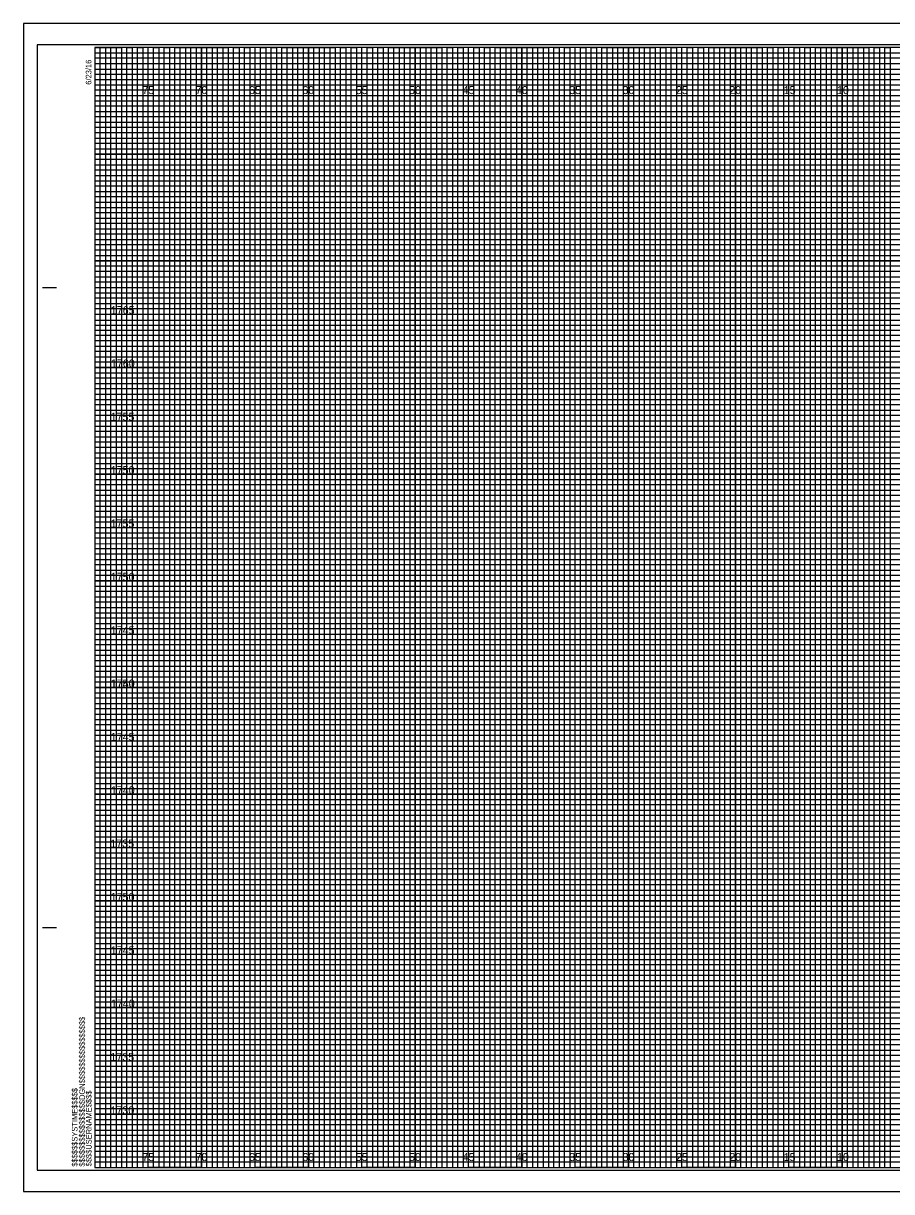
# Model space of a CAD drawing. Extents: x -7 to 162, y -2 to 217.
# Drawn here: x -6.7 to 74.6, y 107.7 to 217.2 of the extents above; entities that cross this region are included whole.
import ezdxf

# ---------------------------------------------------------------- set-up
doc = ezdxf.new("R2010")
doc.units = 0
for name, color, linetype in [('Prop XS Elevation Labels', 7, 'Continuous'), ('Prop XS Offset Labels', 7, 'Continuous'), ('Sheet Cross Section CELL', 7, 'Continuous'), ('Sheet Cross Section Grid Major CELL', 7, 'Continuous'), ('Sheet Cross Section Grid Middle CELL', 7, 'Continuous'), ('Sheet Cross Section Grid Minor 1 CELL', 7, 'Continuous'), ('Sheet Cross Section Grid Minor 2 CELL', 7, 'Continuous'), ('Sheet Cutting Line CELL', 7, 'Continuous'), ('Sheet DOT Grid CELL', 7, 'Continuous'), ('Sheet Plot Border Inside CELL', 7, 'Continuous'), ('Sheet Plot Border Outside CELL', 7, 'Continuous')]:
    doc.layers.add(name, color=color, linetype=linetype)

msp = doc.modelspace()

# ---------------------------------------------------------------- linework, layer by layer
at = {"layer": 'Sheet Cross Section CELL'}
for p, q in [((-4.9, 192.5), (-3.65, 192.5)), ((-4.85, 192.5), (-3.6, 192.5)), ((-4.9, 132.5), (-3.65, 132.5)), ((-4.85, 132.5), (-3.6, 132.5)), ((0, 110), (0, 110)), ((0, 110), (0, 110)), ((0, 110), (0, 110)), ((0, 110), (0, 110)), ((0, 110), (0, 110)), ((0, 110), (0, 110)), ((0, 110), (0, 110))]:
    msp.add_line(p, q, dxfattribs=at)
msp.add_lwpolyline([(160, 215), (0, 215), (0, 110), (160, 110)], close=True, dxfattribs=at)
at = {"layer": 'Sheet Cross Section Grid Major CELL'}
for p, q in [((5, 215), (0, 215)), ((5, 110), (5, 215)), ((15, 215), (10, 215)), ((10, 215), (10, 110)), ((15, 110), (15, 215)), ((25, 215), (20, 215)), ((20, 215), (20, 110)), ((25, 110), (25, 215)), ((35, 215), (30, 215)), ((30, 215), (30, 110)), ((35, 110), (35, 215)), ((45, 215), (40, 215)), ((40, 215), (40, 110)), ((45, 110), (45, 215)), ((55, 215), (50, 215)), ((50, 215), (50, 110)), ((55, 110), (55, 215)), ((65, 215), (60, 215)), ((60, 215), (60, 110)), ((65, 110), (65, 215)), ((75, 215), (70, 215)), ((70, 215), (70, 110)), ((10, 110), (5, 110)), ((20, 110), (15, 110)), ((30, 110), (25, 110)), ((40, 110), (35, 110)), ((50, 110), (45, 110)), ((60, 110), (55, 110)), ((70, 110), (65, 110))]:
    msp.add_line(p, q, dxfattribs=at)
for points in [[(0, 210), (160, 210), (160, 205), (0, 205)], [(0, 200), (160, 200), (160, 195), (0, 195)], [(0, 190), (160, 190), (160, 185), (0, 185)], [(0, 180), (160, 180), (160, 175), (0, 175)], [(0, 170), (160, 170), (160, 165), (0, 165)], [(0, 160), (160, 160), (160, 155), (0, 155)], [(0, 150), (160, 150), (160, 145), (0, 145)], [(0, 140), (160, 140), (160, 135), (0, 135)], [(0, 130), (160, 130), (160, 125), (0, 125)], [(0, 120), (160, 120), (160, 115), (0, 115)]]:
    msp.add_lwpolyline(points, dxfattribs=at)
at = {"layer": 'Sheet Cross Section Grid Middle CELL'}
for points in [[(0, 215), (2.5, 215), (2.5, 110), (7.5, 110), (7.5, 215), (12.5, 215), (12.5, 110), (17.5, 110), (17.5, 215), (22.5, 215), (22.5, 110), (27.5, 110), (27.5, 215), (32.5, 215), (32.5, 110), (37.5, 110), (37.5, 215), (42.5, 215), (42.5, 110), (47.5, 110), (47.5, 215), (52.5, 215), (52.5, 110), (57.5, 110), (57.5, 215), (62.5, 215), (62.5, 110), (67.5, 110), (67.5, 215), (72.5, 215), (72.5, 110), (77.5, 110)], [(0, 212.5), (137.5, 212.5)], [(0, 202.5), (160, 202.5), (160, 207.5), (0, 207.5)], [(0, 192.5), (160, 192.5), (160, 197.5), (0, 197.5)], [(0, 182.5), (160, 182.5), (160, 187.5), (0, 187.5)], [(0, 172.5), (160, 172.5), (160, 177.5), (0, 177.5)], [(0, 162.5), (160, 162.5), (160, 167.5), (0, 167.5)], [(0, 152.5), (160, 152.5), (160, 157.5), (0, 157.5)], [(0, 142.5), (160, 142.5), (160, 147.5), (0, 147.5)], [(0, 132.5), (160, 132.5), (160, 137.5), (0, 137.5)], [(0, 122.5), (160, 122.5), (160, 127.5), (0, 127.5)], [(0, 112.5), (160, 112.5), (160, 117.5), (0, 117.5)]]:
    msp.add_lwpolyline(points, dxfattribs=at)
at = {"layer": 'Sheet Cross Section Grid Minor 1 CELL'}
for p, q in [((0, 214.5), (130, 214.5)), ((130, 213.99), (0, 213.99)), ((0, 213.99), (0, 213.5)), ((0, 213.5), (130, 213.5)), ((130, 212.94), (0, 212.94)), ((0, 212.94), (0, 212)), ((0, 212), (160, 212))]:
    msp.add_line(p, q, dxfattribs=at)
for points in [[(0, 211.5), (135, 211.5), (160, 211.5), (160, 211), (0, 211)], [(0, 210.5), (160, 210.5), (160, 209.5), (0, 209.5)], [(0, 209), (160, 209), (160, 208.5), (0, 208.49)], [(0, 208), (160, 208), (160, 207), (0, 207)], [(0, 206.5), (160, 206.5), (160, 206), (0, 206)], [(0, 205.5), (160, 205.5), (160, 204.5), (0, 204.5)], [(0, 204), (160, 204), (160, 203.5), (0, 203.5)], [(0, 203), (160, 203), (160, 202), (0, 202)], [(0, 201.5), (160, 201.5), (160, 201), (0, 201)], [(0, 200.5), (160, 200.5), (160, 199.5), (0, 199.5)], [(0, 199), (160, 199), (160, 198.5), (0, 198.5)], [(0, 198), (160, 198), (160, 196.97), (160, 196.5), (160, 196), (0, 196)], [(0, 197), (160, 197), (160, 196.5), (0, 196.5)], [(0, 195.5), (160, 195.5), (160, 194.5), (0, 194.52)], [(0, 194.52), (160, 194.5), (160, 194), (0, 194)], [(0, 193.5), (160, 193.5), (160, 193), (0, 193)], [(0, 192), (160, 192), (160, 191.5), (0, 191.5)], [(0, 191), (160, 191), (160, 190.5), (0, 190.5)], [(-0.04, 189.44), (160, 189.44), (160, 188.94), (-0.04, 188.94)], [(0, 188.5), (160, 188.5), (160, 188), (0, 188)], [(0, 187), (160, 187), (160, 186.5), (0, 186.5)], [(0, 186), (160, 186), (160, 185.5), (0, 185.5)], [(0, 184.5), (160, 184.5), (160, 184), (0, 184)], [(0, 183.5), (160, 183.5), (160, 183), (0, 183)], [(0, 182), (160, 182), (160, 181.5), (0, 181.5)], [(0, 181), (160, 181), (160, 180.5), (0, 180.5)], [(0, 179.5), (160, 179.5), (160, 178.99), (0, 179)], [(0, 178.5), (160, 178.5), (160, 178), (0, 178)], [(0, 177), (160, 177), (160, 176.5), (0, 176.5)], [(0, 176), (160, 176), (160, 175.5), (0, 175.5)], [(0, 174.5), (160, 174.5), (160, 174), (0, 174)], [(0, 173.5), (160, 173.5), (160, 173), (0, 173)], [(0, 172), (160, 172), (160, 171.5), (0, 171.5)], [(0, 171), (160, 171), (160, 170.5), (0, 170.5)], [(0, 169.5), (160, 169.5), (160, 169), (0, 169)], [(0, 168.5), (160.03, 168.46), (160, 168), (0, 168)], [(0, 167), (160, 167), (160, 166.5), (0, 166.5)], [(0, 166), (160, 166), (160, 165.5), (0, 165.5)], [(0, 164.5), (160, 164.5), (160, 164), (0, 164)], [(0, 163.5), (160, 163.5), (160, 163), (0, 163)], [(0, 162), (160, 162), (160, 161.5), (0, 161.5)], [(0, 161), (160, 161), (160, 160.5), (0, 160.5)], [(0, 159.5), (160, 159.5), (160, 159), (0, 159)], [(0, 158.5), (160, 158.5), (160, 158), (0, 158)], [(0, 157), (160, 157), (160, 156.5), (0, 156.5)], [(0, 156), (160, 156), (160, 155.5), (0, 155.5)], [(0, 154.5), (160, 154.5), (160, 154), (0, 154)], [(0, 153.5), (160, 153.5), (160, 153), (0, 153)], [(0, 152), (160, 152), (160, 151.5), (0, 151.5)], [(0, 151), (160, 151), (160, 150.5), (0, 150.5)], [(0, 149.5), (160, 149.5), (160, 148.99), (0, 149)], [(0, 148.5), (160, 148.5), (160, 148), (0, 148)], [(0, 147), (160, 147), (160, 146.5), (0, 146.5)], [(0, 146), (160, 146), (160, 145.5), (0, 145.5)], [(0, 144.5), (160, 144.5), (160, 144), (0, 144)], [(0, 143.5), (160, 143.5), (160, 143), (0, 143)], [(0, 142), (160, 142), (160, 141.5), (0, 141.5)], [(0, 141), (160, 141), (160, 140.5), (0, 140.5)], [(0, 139.5), (160, 139.5), (160, 139), (0, 139)], [(0, 138.5), (160.03, 138.46), (160, 138), (0, 138)], [(0, 137), (160, 137), (160, 136.5), (0, 136.5)], [(0, 136), (160, 136), (160, 135.5), (0, 135.5)], [(0, 134.5), (160, 134.5), (160, 134), (0, 134)], [(0, 133.5), (160, 133.5), (160, 133), (0, 133)], [(0, 132), (160, 132), (160, 131.5), (0, 131.5)], [(0, 131), (160, 131), (160, 130.5), (0, 130.5)], [(0, 129.5), (160, 129.5), (160, 129), (0, 129)], [(0, 128.5), (160, 128.5), (160, 128), (0, 128)], [(0, 127), (160, 127), (160, 126.5), (0, 126.5)], [(0, 126), (160, 126), (160, 125.5), (0, 125.5)], [(0, 124.5), (160, 124.5), (160, 124), (0, 124)], [(0, 123.5), (160, 123.5), (160, 123), (0, 123)], [(0, 122), (160, 122), (160, 121.5), (0, 121.5)], [(0, 121), (160, 121), (160, 120.5), (0, 120.5)], [(0, 119.5), (160, 119.5), (160, 119), (0, 119)], [(0, 118.5), (160, 118.5), (160, 118), (0, 118)], [(0, 117), (160, 117), (160, 116.5), (0, 116.5)], [(0, 116), (160, 116), (160, 115.5), (0, 115.5)], [(0, 114.5), (160, 114.5), (160, 114), (0, 114)], [(0, 113.5), (160, 113.5), (160, 113), (0, 113)], [(0, 112), (160, 112), (160, 111.5), (0, 111.5)], [(0, 111), (160, 111), (160, 110.5), (0, 110.5)]]:
    msp.add_lwpolyline(points, dxfattribs=at)
at = {"layer": 'Sheet Cross Section Grid Minor 2 CELL'}
for points in [[(0, 110), (0.5, 110), (0.5, 215), (1, 215), (1, 110)], [(1, 110), (1.5, 110), (1.5, 215), (2, 215), (2, 110)], [(2.5, 110), (3, 110), (3, 215), (3.5, 215), (3.5, 110)], [(3.5, 110), (4, 110), (4, 215), (4.5, 215), (4.5, 110)], [(5, 110), (5.5, 110), (5.5, 215), (6, 215), (6, 110)], [(6, 110), (6.5, 110), (6.5, 215), (7, 215), (7, 110)], [(7.5, 110), (8, 110), (8, 215), (8.5, 215), (8.5, 110)], [(8.5, 110), (9, 110), (9, 215), (9.5, 215), (9.5, 110)], [(10, 110), (10.5, 110), (10.5, 215), (11, 215), (11, 110)], [(11, 110), (11.5, 110), (11.5, 215), (12, 215), (12, 110)], [(12.5, 110), (13, 110), (13, 215), (13.5, 215), (13.5, 110)], [(13.5, 110), (14, 110), (14, 215), (14.5, 215), (14.5, 110)], [(15, 110), (15.5, 110), (15.5, 215), (16, 215), (16, 110)], [(16, 110), (16.5, 110), (16.5, 215), (17, 215), (17, 110)], [(17.5, 110), (18, 110), (18, 215), (18.5, 215), (18.5, 110)], [(18.5, 110), (19, 110), (19, 215), (19.5, 215), (19.5, 110)], [(20, 110), (20.5, 110), (20.5, 215), (21, 215), (21, 110)], [(21, 110), (21.5, 110), (21.5, 215), (22, 215), (22, 110)], [(22.5, 110), (23, 110), (23, 215), (23.5, 215), (23.5, 110)], [(23.5, 110), (24, 110), (24, 215), (24.5, 215), (24.5, 110)], [(25, 110), (25.5, 110), (25.5, 215), (26, 215), (26, 110)], [(26, 110), (26.5, 110), (26.5, 215), (27, 215), (27, 110)], [(27.5, 110), (28, 110), (28, 215), (28.5, 215), (28.5, 110)], [(28.5, 110), (29, 110), (29, 215), (29.5, 215), (29.5, 110)], [(30, 110), (30.5, 110), (30.5, 215), (31, 215), (31, 110)], [(31, 110), (31.5, 110), (31.5, 215), (32, 215), (32, 110)], [(32.5, 110), (33, 110), (33, 215), (33.5, 215), (33.5, 110)], [(33.5, 110), (34, 110), (34, 215), (34.5, 215), (34.5, 110)], [(35, 110), (35.5, 110), (35.5, 215), (36, 215), (36, 110)], [(36, 110), (36.5, 110), (36.5, 215), (37, 215), (37, 110)], [(37.5, 110), (38, 110), (38, 215), (38.5, 215), (38.5, 110)], [(38.5, 110), (39, 110), (39, 215), (39.5, 215), (39.5, 110)], [(40, 110), (40.5, 110), (40.5, 215), (41, 215), (41, 110)], [(41, 110), (41.5, 110), (41.5, 215), (42, 215), (42, 110)], [(42.5, 110), (43, 110), (43, 215), (43.5, 215), (43.5, 110)], [(43.5, 110), (44, 110), (44, 215), (44.5, 215), (44.5, 110)], [(45, 110), (45.5, 110), (45.5, 215), (46, 215), (46, 110)], [(46, 110), (46.5, 110), (46.5, 215), (47, 215), (47, 110)], [(47.5, 110), (48, 110), (48, 215), (48.5, 215), (48.5, 110)], [(48.5, 110), (49, 110), (49, 215), (49.5, 215), (49.5, 110)], [(50, 110), (50.5, 110), (50.5, 215), (51, 215), (51, 110)], [(51, 110), (51.5, 110), (51.5, 215), (52, 215), (52, 110)], [(52.5, 110), (53, 110), (53, 215), (53.5, 215), (53.5, 110)], [(53.5, 110), (54, 110), (54, 215), (54.5, 215), (54.5, 110)], [(55, 110), (55.5, 110), (55.5, 215), (56, 215), (56, 110)], [(56, 110), (56.5, 110), (56.5, 215), (57, 215), (57, 110)], [(57.5, 110), (58, 110), (58, 215), (58.5, 215), (58.5, 110)], [(58.5, 110), (59, 110), (59, 215), (59.5, 215), (59.5, 110)], [(60, 110), (60.5, 110), (60.5, 215), (61, 215), (61, 110)], [(61, 110), (61.5, 110), (61.5, 215), (62, 215), (62, 110)], [(62.5, 110), (63, 110), (63, 215), (63.5, 215), (63.5, 110)], [(63.5, 110), (64, 110), (64, 215), (64.5, 215), (64.5, 110)], [(65, 110), (65.5, 110), (65.5, 215), (66, 215), (66, 110)], [(66, 110), (66.5, 110), (66.5, 215), (67, 215), (67, 110)], [(67.5, 110), (68, 110), (68, 215), (68.5, 215), (68.5, 110)], [(68.5, 110), (69, 110), (69, 215), (69.5, 215), (69.5, 110)], [(70, 110), (70.5, 110), (70.5, 215), (71, 215), (71, 110)], [(71, 110), (71.5, 110), (71.5, 215), (72, 215), (72, 110)], [(72.5, 110), (73, 110), (73, 215), (73.5, 215), (73.5, 110)], [(73.5, 110), (74, 110), (74, 215), (74.5, 215), (74.5, 110)]]:
    msp.add_lwpolyline(points, dxfattribs=at)
at = {"layer": 'Sheet Cutting Line CELL'}
for p, q in [((161.65, 217.25), (-6.7, 217.25)), ((-6.7, 217.25), (-6.7, 107.75)), ((-6.7, 107.75), (161.65, 107.75))]:
    msp.add_line(p, q, dxfattribs=at)
at = {"layer": 'Sheet DOT Grid CELL'}
for p, q in [((5, 110), (5, 215)), ((10, 110), (10, 215)), ((15, 110), (15, 215)), ((20, 110), (20, 215)), ((25, 110), (25, 215)), ((30, 110), (30, 215)), ((35, 110), (35, 215)), ((40, 110), (40, 215)), ((45, 110), (45, 215)), ((50, 110), (50, 215)), ((55, 110), (55, 215)), ((60, 110), (60, 215)), ((65, 110), (65, 215)), ((70, 110), (70, 215)), ((0, 210), (160, 210)), ((0, 205), (160, 205)), ((0, 200), (160, 200)), ((0, 195), (160, 195)), ((0, 190), (160, 190)), ((0, 185), (160, 185)), ((0, 180), (160, 180)), ((0, 175), (160, 175)), ((0, 170), (160, 170)), ((0, 165), (160, 165)), ((0, 160), (160, 160)), ((0, 155), (160, 155)), ((0, 150), (160, 150)), ((0, 145), (160, 145)), ((0, 140), (160, 140)), ((0, 135), (160, 135)), ((0, 130), (160, 130)), ((0, 125), (160, 125)), ((0, 120), (160, 120)), ((0, 115), (160, 115))]:
    msp.add_line(p, q, dxfattribs=at)
at = {"layer": 'Sheet Plot Border Inside CELL'}
msp.add_lwpolyline([(-5.4, 109.75), (161.2, 109.75), (161.2, 215.25), (-5.4, 215.25)], close=True, dxfattribs=at)
at = {"layer": 'Sheet Plot Border Outside CELL'}
msp.add_lwpolyline([(-6.7, 107.75), (161.65, 107.75), (161.65, 217.25), (-6.7, 217.25)], close=True, dxfattribs=at)

# ---------------------------------------------------------------- texts
at = {"layer": 'Prop XS Elevation Labels'}
for s, p in [('1765', (1.49, 190)), ('1760', (1.5, 185)), ('1755', (1.47, 180)), ('1750', (1.48, 175)), ('1755', (1.47, 170)), ('1750', (1.48, 165)), ('1745', (1.49, 160)), ('1750', (1.48, 155)), ('1740', (1.5, 155)), ('1745', (1.49, 150)), ('1740', (1.5, 145)), ('1735', (1.45, 140)), ('1750', (1.48, 135)), ('1745', (1.49, 130)), ('1740', (1.5, 125)), ('1735', (1.45, 120)), ('1730', (1.46, 115))]:
    msp.add_text(s, height=0.75, dxfattribs=at).set_placement(p)
at = {"layer": 'Prop XS Offset Labels'}
for s, p in [('75', (4.44, 210.62)), ('70', (9.43, 210.62)), ('65', (14.44, 210.62)), ('60', (19.43, 210.62)), ('55', (24.44, 210.62)), ('50', (29.43, 210.62)), ('45', (34.44, 210.62)), ('40', (39.43, 210.62)), ('35', (44.44, 210.62)), ('30', (49.43, 210.62)), ('25', (54.44, 210.62)), ('20', (59.43, 210.62)), ('15', (64.53, 210.62)), ('10', (69.52, 210.62)), ('75', (4.44, 110.62)), ('70', (9.43, 110.62)), ('65', (14.44, 110.62)), ('60', (19.43, 110.62)), ('55', (24.44, 110.62)), ('50', (29.43, 110.62)), ('45', (34.44, 110.62)), ('40', (39.43, 110.62)), ('35', (44.44, 110.62)), ('30', (49.43, 110.62)), ('25', (54.44, 110.62)), ('20', (59.43, 110.62)), ('15', (64.53, 110.62)), ('10', (69.52, 110.62))]:
    msp.add_text(s, height=0.75, dxfattribs=at).set_placement(p)
at = {"layer": 'Sheet Cross Section CELL'}
for s, p in [('6/23/16', (-0.33, 211.5)), ('$$$$$$$$$$$$$$$$DGN$$$$$$$$$$$$$$$$', (-0.94, 110.09)), ('$$$$$$SYSTIME$$$$$', (-1.63, 110.09)), ('$$$$USERNAME$$$$', (-0.31, 110.12))]:
    msp.add_text(s, height=0.525, rotation=90, dxfattribs=at).set_placement(p)

doc.saveas('drawing.dxf')
